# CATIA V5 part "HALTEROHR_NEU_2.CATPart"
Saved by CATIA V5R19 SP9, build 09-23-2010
Part number: P_XXX_HALTEROHR_244_9_12_8,4_LAENGE_P_XXX_SCHEIBE_244_10_8,4_23_4_M8
Description: MOEGLICHE LAENGEN  27 / 33 / 38 / 44 / 48 / 61 / 63 / 72 / 80 / 90 / 100  
Bounding box of the stored display mesh (mm): x -8.498 to 8.498, y -8.491 to 8.491, z -89 to 12
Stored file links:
  D:\#work\TMP\Neuer Ordner\HALTEROHR_NEU_2.CATPart
  D:\#work\TMP\Neuer Ordner\HALTEROHR_SCHEIBE.xls
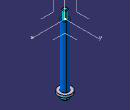
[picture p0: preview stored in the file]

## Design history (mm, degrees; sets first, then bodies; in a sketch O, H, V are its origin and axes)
Parameters
  `244_9` = "ROHR_244_9_10_SCHEIBE_244_10_064_17_3" {design table}
  GEWINDEBESCHREIBUNG = "M6" {design table}
  MASS_HUB = 5 mm
  ROHR_INNEN = 6.4 mm {design table}
  ROHR_AUSSEN = 10 mm {design table}
  ROHRLAENGE1 = 80 mm
  ROHRLAENGE2 = 100 mm
  ROHRLAENGE3 = 60 mm
  SCHEIBE_DICKE = 3 mm {design table}
  SCHEIBE_AUSSEN = 17 mm {design table}
  SCHEIBE_INNEN = 6.4 mm {design table}
  SCHRAUBENGEWINDELAENGE = 12 mm {design table}
  SCHRAUBENGEWINDEDURCHMESSER = 6 mm {design table}
  SCHRAUBENKOPFHOEHE = 6 mm {design table}
  SCHRAUBENKOPFDURCHMESSER = 10 mm {design table}
  SCHRAUBEN_RADIUS = 0.8 mm {design table}
  SCHRAUBEN_FASE = 0.8 mm {design table}
  ABZUG_D_1 = 11 mm {design table}
  ABZUG_D_2 = 18 mm {design table}
  GEWINDETIEFE = 15 mm {design table}
  BOHRUNGSTIEFE = 20 mm {design table}
AxisSystem1: origin (0, 0, 0), X (1, 0, 0), Y (0, 1, 0), Z (0, 0, 1)
Set1 "Maste_Info"
  Set3 "Abgeh._Geo"
    Set4 "Skizzen_Koerper"
      Sketch1 on YZ plane of AxisSystem1, origin (0, 0, 0), H (0, 1, 0), V (0, 0, 1)
        axis line L1 (0, -78.0323) -> (0, -64.9353)
        point P1 (0, -78.0323)
        point P3 (5.85, -81.5)
        line L2 (8.5, -80) -> (8.5, -83)
        line L3 (8.5, -83) -> (3.2, -83)
        line L4 (3.2, -83) -> (3.2, -80)
        line L5 (3.2, -80) -> (8.5, -80)
        reference projected line E1 (6, -80) -> (-6, -80) from edge [face of Shaft1 from Sketch2.L2 | face of Shaft1 from Sketch2.L3]
        length L2 = 3 {= SCHEIBE_DICKE}
        distance L5 E1 = 0
        distance L1 L4 = 3.2 {= SCHEIBE_INNEN /2}
        distance L1 L2 = 8.5 {= SCHEIBE_AUSSEN /2}
        coincidence: P1 V
        vertical: L1 V, L2 V, L4 V
        horizontal: L3 H, L5 H
        equidistance: L2 L4 P3, L3 L5 P3
      Sketch2 on YZ plane of AxisSystem1, origin (0, 0, 0), H (0, 1, 0), V (0, 0, 1)
        axis line L1 (0, 24.625) -> (0, -54.8472)
        point P1 (0, 24.625)
        point P3 (4.1, -40)
        line L2 (5, 0) -> (5, -80)
        line L3 (5, -80) -> (3.2, -80)
        line L4 (3.2, -80) -> (3.2, 0)
        line L5 (3.2, 0) -> (5, 0)
        distance L1 L4 = 3.2 {= ROHR_INNEN /2}
        distance L2 L1 = 5 {= ROHR_AUSSEN /2}
        distance L5 H = 0
        length L2 = 80
        length L2 = 80 (reference)
        coincidence: P1 V
        vertical: L1 V, L2 V, L4 V
        horizontal: L3 H, L5 H
        equidistance: L2 L4 P3, L3 L5 P3
      Sketch3 on YZ plane of AxisSystem1, origin (0, 0, 0), H (0, 1, 0), V (0, 0, 1)
        point P1 (2.5, -86)
        line L1 (5, -83) -> (5, -88.2)
        line L2 (4.2, -89) -> (0, -89)
        line L3 (3, -83) -> (5, -83)
        point P2 (5, -83)
        point P3 (5, -89)
        axis line L4 (0, -26.2242) -> (0, -89)
        point P4 (0, -26.2242)
        reference projected line E1 (11.5, -83) -> (-11.5, -83) from edge [face of Shaft2 from Sketch1.L3 | face of Shaft2 from Sketch1.L2]
        arc A1 centre (4.2, -88.2) radius 0.8 from (5, -88.2) to (4.2, -89) cw
        line L5 (3, 12) -> (0, 12)
        point P9 (0, 12)
        reference projected line E2 (6, 0) -> (-6, 0) from edge [face of Shaft1 from Sketch2.L5 | face of Shaft1 from Sketch2.L2]
        line L6 (3, 12) -> (3, -83)
        distance L3 E1 = 0
        distance L4 L1 = 5 {= SCHRAUBENKOPFDURCHMESSER /2}
        distance P2 P3 = 6 {= SCHRAUBENKOPFHOEHE}
        radius A1 = 0.8 {= SCHRAUBEN_RADIUS}
        distance L5 E2 = 12 {= SCHRAUBENGEWINDELAENGE}
        distance L6 L4 = 3 {= SCHRAUBENGEWINDEDURCHMESSER /2}
        vertical: L1 V, L4 V, L6 V
        horizontal: L2 H, L3 H, L5 H
        equidistance: L2 L3 P1
        coincidence: P4 V, L1 P3, L2 P3, P9 V
        tangency: A1 L1, A1 L2
Body1 (main body)
  Shaft1: profile Sketch2, axis Sketch2.L1, angle 360
  Sketch4 on XY plane of AxisSystem1, origin (0, 0, 0), H (1, 0, 0), V (0, 1, 0)
    point P1 (70.3564, 15.2272)
    point P2 (0, 0)
    coincidence: P2 O
  UserPattern1: of the body so far, copies 2, at the points of Sketch4, deactivated
Body2
  Shaft2: profile Sketch1, axis Sketch1.L1, angle 360
  UserPattern2: of the body so far, copies 2, at the points of Sketch4, deactivated
Body3
  Shaft3: profile Sketch3, axis Sketch3.L4, angle 360
  UserPattern3: of the body so far, copies 2, at the points of Sketch4, deactivated
  Chamfer1 "SCHRAUBENFASE": length 0.8 {= SCHRAUBEN_FASE}, angle 45, on edge [face of Shaft3 from Sketch3.L5 | face of Shaft3 from Sketch3.L6]
Body4 "ABZUGSKOERPER_HALTEROHR"
  Sketch5 on ZX plane of AxisSystem1, origin (0, 0, 0), H (1, 0, 0), V (0, 0, 1)
    axis line L1 (0, 16.9793) -> (0, -51.3262)
    point P1 (0, 16.9793)
    line L2 (0, 0) -> (5.5, 0)
    line L3 (5.5, 0) -> (5.5, -75)
    line L4 (5.5, -75) -> (9, -75)
    line L5 (9, -75) -> (9, -175)
    line L6 (9, -175) -> (0, -175)
    point P7 (0, -175)
    reference projected line E1 (-8.5, -80) -> (8.5, -80) from edge [face of Shaft2 from Sketch1.L2 | face of Shaft2 from Sketch1.L5]
    distance L3 L1 = 5.5 {= ABZUG_D_1 /2}
    distance L5 L1 = 9 {= ABZUG_D_2 /2}
    distance L4 E1 = 5 {= MASS_HUB}
    length L5 = 100
    coincidence: P1 V, P7 L1
    vertical: L1 V, L3 V, L5 V
    horizontal: L2 H, L4 H, L6 H
  Groove1: profile Sketch5, axis Sketch5.L1, angle 360
  Sketch6 on face of Groove1 from Sketch5.L2, origin (-75.215, 25.6591, 0), H (1, 0, 0), V (0, -1, 0)
    point P1 (75.215, 25.6591)
    reference projected point E1 (75.215, 25.6591)
    coincidence: E1 P1
  Hole1 "Bohrung_M8": placed by Sketch6, at (0, 0, 0) direction (0, 0, 1), diameter 4.917, depth 20 {= BOHRUNGSTIEFE}, V-bottom angle 120, threaded "M6", thread diameter 6, thread depth 15 {= GEWINDETIEFE}, pitch 1
Relations
  design table, configuration 1, drives `244_9`, GEWINDEBESCHREIBUNG, ROHR_INNEN, ROHR_AUSSEN, SCHEIBE_DICKE, SCHEIBE_AUSSEN, SCHEIBE_INNEN, SCHRAUBENGEWINDELAENGE, SCHRAUBENGEWINDEDURCHMESSER, SCHRAUBENKOPFHOEHE, SCHRAUBENKOPFDURCHMESSER, SCHRAUBEN_RADIUS, SCHRAUBEN_FASE, ABZUG_D_1, ABZUG_D_2, GEWINDETIEFE, BOHRUNGSTIEFE
  Hole1.ThreadDescription = GEWINDEBESCHREIBUNG
  rule:
    /*Regel erzeugt von: KH 11.12.2014*/
    if SCHRAUBENGEWINDEDURCHMESSER ==6mm
    	{Sketch2.length(L2) =ROHRLAENGE1
    	ROHRLAENGE1 .Show=true
    	ROHRLAENGE2 .Show=false}
    if SCHRAUBENGEWINDEDURCHMESSER ==8mm
    	{Sketch2.length(L2) =ROHRLAENGE2
    	ROHRLAENGE1 .Show=false
    ROHRLAENGE2 .Show=true}
    if SCHRAUBENGEWINDEDURCHMESSER ==10mm
    	{Sketch2.length(L2) =ROHRLAENGE3
    	ROHRLAENGE1 .Show=false
    	ROHRLAENGE2 .Show=false
    	ROHRLAENGE3 .Show=true}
